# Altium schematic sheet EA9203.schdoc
size 127 x 101 mm
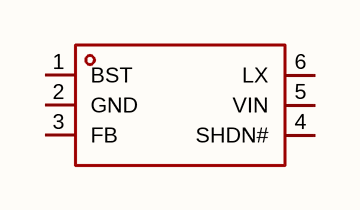
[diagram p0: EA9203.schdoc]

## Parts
U?  ea9203  [SOT-23-6_L2.9-W1.6-P0.95-LS2.8-BL]  (value not drawn)

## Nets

Not connected (* = marked no-connect by the designer): U? 1(BST) 2(GND) 3(FB) 4(SHDN#) 5(VIN) 6(LX)

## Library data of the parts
U? = ea9203: 功能类型:降压型;工作电压:4.5V~24V;输出电压:800mV~8V;输出电流:1.2A;输出类型:可调;; Manufacturer: everanalog(申风); AddInBom: yes; ModelId: 18da8f6c14a34920b3e136b5c401a119; ModelName: SOT-23-6_L2.9-W1.6-H1.5-LS2.8-P0.95; ModelTransform: 110.236,113.364,0,90,0,0,0.0005,0.0005,0; Function: 降压型; Output Current: 1.2A; Frequency - Switching: 1MHz; Synchronous Rectifier: 是; Number of Outputs: 1; Topology: 降压式; Quiescent Current: 450uA; Switch tube (built-in/external): 内置; Output Type: 可调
